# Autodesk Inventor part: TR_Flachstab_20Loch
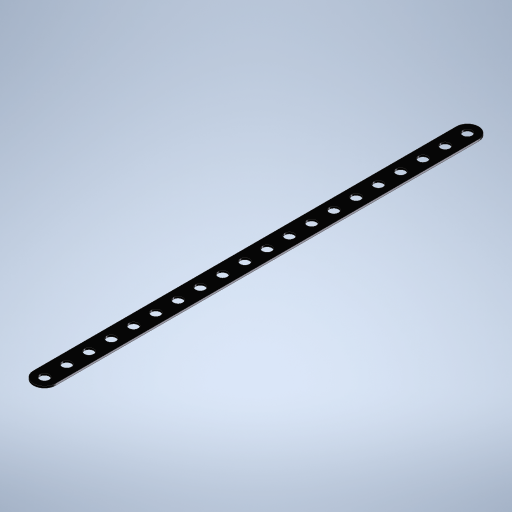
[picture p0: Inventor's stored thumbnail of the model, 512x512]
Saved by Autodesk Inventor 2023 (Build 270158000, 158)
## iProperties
Created: 2023-11
Part Number: TR_Flachstab_20Loch
Material: Edelstahl
Document SubType Name: Modeling
Designer: Admin
Density: 8 g/cm^3
Appearance: Halbpoliert
Author: Admin
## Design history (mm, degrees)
sketch "Skizze1"
  geometry: L1 (0, 95)-(0, -95); L2 (-5, 95)-(-5, -95); L3 (5, -95)-(5, 95); A1 r 5 centre (0, 95) between (5, 95) and (-5, 95); A2 r 5 centre (0, -95) between (-5, -95) and (5, -95); 3 further points
  constraints: 8 end point, 4 point on circle, 4 tangent, 2 centre point, 2 midpoint, 1 horizontal alignment, 1 parallel, 1 vertical, 1 vertical alignment
  dimensions: "d0" = 190 distance of L1.start L1.end (computed from Loch, Einheitsmaß); "d1" = 5 radius of A1 (= 0.5 x Einheitsmaß)
extrude "Extrusion1" new body sketch "Skizze1" distance "d5" = 0.8 (= Dicke); taper "d6" = 0 deg
sketch "Skizze2"
  geometry: C1 r 2.075 at (0, 95); A1 r 5 centre (0, 95) between (5, 95) and (-5, 95) reference; 1 further point
  constraints: 1 centre point, 1 coincident
  dimensions: "d7" = 4.15 diameter of C1 (= 2 x Radius)
extrude "Extrusion2" cut sketch "Skizze2" stored distance "d8" = 10; taper "d9" = 0 deg
node "Volumenkörper1"
pattern_linear "Rechteckige Anordnung1" dims "d12" = 10 (= Einheitsmaß)
other parameters: "Einheitsmaß" = 10 [user parameter; used in 3 equation terms], "Radius" = 2.075 [user parameter; used in 1 equation term], "Fasen" = 0.5 [user parameter], "Dicke" = 0.8 [user parameter; used in 1 equation term]
